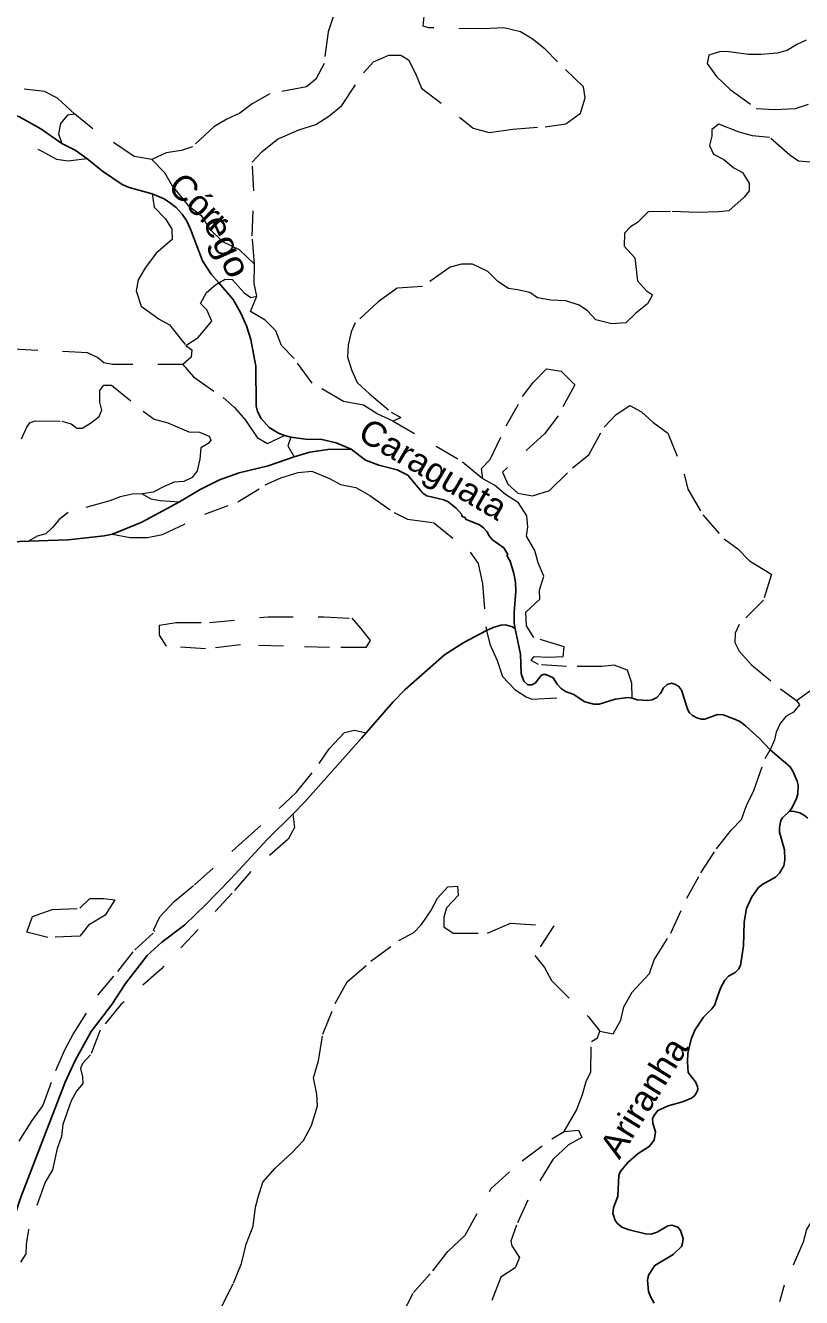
# Model space of a CAD drawing. Extents: x 344.9 to 371, y 7566.4 to 7594.3.
# Drawn here: x 359.71 to 362.82, y 7569.18 to 7574.28 of the extents above; entities that cross this region are included whole.
import ezdxf
from ezdxf.enums import TextEntityAlignment as Align

# ---------------------------------------------------------------- set-up
doc = ezdxf.new("R2010")
doc.units = 0
doc.header["$LTSCALE"] = 0.04
doc.linetypes.add('SHORT_DASHED', pattern=[2.7, 1.5, -1.2])
for name, color, linetype, lineweight in [('17', 7, 'SHORT_DASHED', 13), ('21', 7, 'SHORT_DASHED', 13), ('7', 7, 'Continuous', 25)]:
    doc.layers.add(name, color=color, linetype=linetype, lineweight=lineweight)
doc.layers.add('61', color=7, linetype='Continuous')

msp = doc.modelspace()

# ---------------------------------------------------------------- linework, layer by layer
at = {"layer": '17'}
for points in [[(359.9089, 7573.9225), (359.8797, 7573.9176), (359.8525, 7573.8846), (359.8447, 7573.8438), (359.8579, 7573.8042)], [(360.2178, 7573.741), (360.2676, 7573.6881), (360.2988, 7573.6356), (360.361, 7573.5579), (360.4154, 7573.517), (360.4484, 7573.4626), (360.5009, 7573.4121), (360.567, 7573.381), (360.6284, 7573.3223)], [(360.3538, 7572.9965), (360.4023, 7573.0285), (360.4577, 7573.0936), (360.4373, 7573.1393), (360.412, 7573.1636), (360.4363, 7573.2083), (360.4723, 7573.2394), (360.485, 7573.2467)], [(360.485, 7573.2467), (360.5112, 7573.2617), (360.5394, 7573.2607), (360.587, 7573.2073), (360.6132, 7573.1878), (360.6378, 7573.1937)], [(360.3421, 7572.9206), (360.3844, 7572.8711), (360.5031, 7572.7876), (360.5485, 7572.748), (360.5925, 7572.6967), (360.6394, 7572.6278), (360.6804, 7572.6044), (360.7483, 7572.6354)], [(361.1825, 7572.6938), (361.4606, 7572.5308), (361.5422, 7572.4628)], [(360.7742, 7572.6294), (360.7611, 7572.5941), (360.7863, 7572.551)], [(362.7973, 7571.5743), (362.9208, 7571.6646), (362.9714, 7571.7215), (363.0813, 7571.8908), (363.142, 7572.0033), (363.1724, 7572.1045), (363.2128, 7572.1677), (363.2596, 7572.2498), (363.3076, 7572.2903), (363.3606, 7572.3471), (363.444, 7572.4217), (363.4706, 7572.4444), (363.5199, 7572.4747), (363.568, 7572.5253), (363.5844, 7572.5493), (363.6311, 7572.5632), (363.6948, 7572.5426)], [(360.1786, 7572.4028), (360.2136, 7572.3821), (360.2503, 7572.3762), (360.3278, 7572.3706)], [(363.5011, 7570.3979), (363.3768, 7570.4345), (363.3159, 7570.429), (363.2845, 7570.3921), (363.2402, 7570.2519), (363.2199, 7570.2057), (363.1646, 7570.1578), (363.1148, 7570.1061), (363.0945, 7570.0342), (363.052, 7569.9456), (363.0354, 7569.8847), (363.0133, 7569.8312), (362.9764, 7569.7233), (362.9616, 7569.6402), (362.886, 7569.5388), (362.8362, 7569.4576), (362.8233, 7569.4059), (362.7477, 7569.2343), (362.7292, 7569.1679)], [(361.8672, 7569.8493), (361.917, 7569.9351), (361.941, 7569.9978), (361.9558, 7570.0495), (361.9742, 7570.0882), (361.9761, 7570.21), (362, 7570.2247), (362.0101, 7570.2504)]]:
    msp.add_lwpolyline(points, dxfattribs=at)
at = {"layer": '21'}
for points in [[(360.9488, 7574.328), (360.9229, 7574.2525), (360.9064, 7574.1252), (360.8734, 7574.0628), (360.8357, 7574.0321), (360.6894, 7574.0038), (360.6187, 7573.9637), (360.5692, 7573.926), (360.5173, 7573.9024), (360.4654, 7573.8718), (360.3805, 7573.7916), (360.3357, 7573.7763), (360.2744, 7573.7669), (360.2178, 7573.741)], [(360.6284, 7573.3223), (360.6189, 7573.4355), (360.626, 7573.6147), (360.6189, 7573.7302), (360.659, 7573.7727), (360.7203, 7573.8222), (360.8052, 7573.8599), (360.8736, 7573.8812), (360.9255, 7573.9142), (360.9774, 7573.9566), (361.0647, 7574.0875), (361.1047, 7574.1323), (361.1661, 7574.1583), (361.2132, 7574.1583), (361.2439, 7574.1394), (361.2722, 7574.0852), (361.2958, 7574.0262), (361.449, 7573.9107), (361.5033, 7573.8659), (361.567, 7573.8483), (361.6613, 7573.8624), (361.791, 7573.8718), (361.8735, 7573.8836), (361.9325, 7573.9261), (361.9514, 7573.9874), (361.9443, 7574.0322), (361.8405, 7574.1312), (361.791, 7574.1831), (361.7391, 7574.2232), (361.692, 7574.2515), (361.6259, 7574.268), (361.5457, 7574.2633), (361.3241, 7574.268), (361.3029, 7574.2751), (361.3076, 7574.3152)], [(362.8354, 7574.2179), (362.7977, 7574.2014), (362.76, 7574.1778), (362.7199, 7574.166), (362.6539, 7574.1613), (362.6043, 7574.1613), (362.5171, 7574.1731), (362.4888, 7574.172), (362.4464, 7574.1578), (362.4393, 7574.1248), (362.477, 7574.0729), (362.5312, 7574.0211), (362.635, 7573.9456), (362.7105, 7573.9409), (362.793, 7573.9456), (362.8449, 7573.9621)], [(359.9089, 7573.9225), (359.8405, 7573.9862), (359.7886, 7574.0134), (359.7061, 7574.0228)], [(359.5008, 7573.9208), (359.5798, 7573.8664), (359.78, 7573.7725), (359.8357, 7573.7416), (359.8822, 7573.7354), (359.9568, 7573.7445)], [(360.2178, 7573.741), (360.147, 7573.7527), (359.982, 7573.8636), (359.9089, 7573.9225)], [(362.852, 7573.7299), (362.8048, 7573.7346), (362.7695, 7573.7581), (362.6893, 7573.8289), (362.6209, 7573.836), (362.5667, 7573.8501), (362.4865, 7573.882), (362.4582, 7573.8608), (362.4582, 7573.8348), (362.4488, 7573.7971), (362.4653, 7573.7617), (362.5054, 7573.7405), (362.5455, 7573.7075), (362.5808, 7573.6886), (362.6068, 7573.6462), (362.6068, 7573.6155), (362.5879, 7573.5896), (362.5266, 7573.5353), (362.4865, 7573.5306), (362.3993, 7573.5283), (362.2932, 7573.533), (362.2035, 7573.5306), (362.1611, 7573.4882), (362.1328, 7573.4717), (362.1092, 7573.4457)], [(360.2195, 7573.6029), (360.2273, 7573.5494), (360.2721, 7573.5027), (360.2974, 7573.4618), (360.2993, 7573.4209), (360.2351, 7573.3664), (360.1922, 7573.308), (360.1631, 7573.2593), (360.1553, 7573.2146), (360.1747, 7573.1542), (360.2467, 7573.1016), (360.2876, 7573.0783), (360.3538, 7572.9965)], [(362.1092, 7573.4457), (362.1069, 7573.3939), (362.1493, 7573.3467), (362.1611, 7573.2549), (362.1965, 7573.2148), (362.2201, 7573.1983), (362.2012, 7573.1629), (362.1541, 7573.1252), (362.114, 7573.0875), (362.0574, 7573.0828), (361.9937, 7573.0993), (361.9607, 7573.1346), (361.9277, 7573.1582), (361.8734, 7573.1747), (361.8145, 7573.1771), (361.7602, 7573.1865), (361.7296, 7573.2077), (361.6801, 7573.2195), (361.6447, 7573.2242), (361.6023, 7573.2525), (361.5622, 7573.2926), (361.5009, 7573.3221), (361.4561, 7573.3221), (361.4113, 7573.3103), (361.3004, 7573.2325), (361.199, 7573.2254), (361.1236, 7573.1712), (361.0316, 7573.0863), (361.0151, 7573.051), (361.0033, 7572.9968), (361.0009, 7572.9496), (361.0174, 7572.8954), (361.0387, 7572.8482), (361.0882, 7572.8023), (361.1755, 7572.7292), (361.2132, 7572.7079), (361.1825, 7572.6938)], [(360.6378, 7573.1937), (360.6269, 7573.2439), (360.6284, 7573.3223)], [(361.1825, 7572.6938), (361.1189, 7572.7221), (361.0646, 7572.7575), (360.9845, 7572.7716), (360.8595, 7572.8447), (360.7864, 7572.9438), (360.7369, 7572.9956), (360.7133, 7573.0546), (360.6708, 7573.097), (360.6119, 7573.1324), (360.6378, 7573.1937)], [(360.3421, 7572.9206), (360.0598, 7572.9206), (360.0248, 7572.9264), (359.9995, 7572.9478), (359.9606, 7572.9673), (359.6277, 7572.9829)], [(360.3538, 7572.9965), (360.3771, 7572.979), (360.3752, 7572.9498), (360.3421, 7572.9206)], [(361.5422, 7572.4628), (361.5365, 7572.5033), (361.5714, 7572.5393), (361.6356, 7572.6743), (361.7009, 7572.7925), (361.7438, 7572.8477), (361.7967, 7572.9028), (361.8552, 7572.8927), (361.9103, 7572.8387), (361.8428, 7572.7149), (361.7888, 7572.6429), (361.62, 7572.4892), (361.6414, 7572.4409), (361.6819, 7572.4048), (361.7404, 7572.3936), (361.809, 7572.4161), (361.9002, 7572.5061), (361.9655, 7572.559), (362.0274, 7572.6698), (362.0758, 7572.7205), (362.1298, 7572.7554), (362.176, 7572.7306), (362.2221, 7572.689), (362.2818, 7572.6457), (362.3471, 7572.4814), (362.3617, 7572.4206), (362.4214, 7572.3188), (362.5069, 7572.222), (362.562, 7572.1815), (362.6093, 7572.1342), (362.6971, 7572.0807), (362.6645, 7571.9772), (362.5677, 7571.8793), (362.5509, 7571.8444), (362.5498, 7571.8073), (362.5678, 7571.7724), (362.6173, 7571.7172), (362.7321, 7571.6216), (362.7973, 7571.5743)], [(359.6958, 7572.6228), (359.7173, 7572.6695), (359.7289, 7572.687), (359.7503, 7572.6948), (359.8574, 7572.6929), (359.8944, 7572.6831), (359.9178, 7572.6656), (359.9392, 7572.6656), (359.9723, 7572.6851), (360.0073, 7572.7123), (360.017, 7572.7366), (360.0092, 7572.7697), (360.0092, 7572.8164), (360.0248, 7572.8379), (360.056, 7572.8379), (360.1825, 7572.7327), (360.2273, 7572.7016), (360.2818, 7572.686), (360.3655, 7572.651), (360.4083, 7572.649), (360.4472, 7572.6335), (360.453, 7572.617), (360.4433, 7572.6033), (360.4141, 7572.5858), (360.4102, 7572.541), (360.3985, 7572.4943), (360.3791, 7572.4671), (360.346, 7572.4515), (360.307, 7572.4496), (360.2662, 7572.432), (360.2233, 7572.4087), (360.1786, 7572.4028)], [(360.0605, 7572.2407), (360.131, 7572.2268), (360.1996, 7572.2279), (360.2604, 7572.2392), (360.4292, 7572.3202), (360.5619, 7572.3697), (360.6711, 7572.4383), (360.733, 7572.4665), (360.8028, 7572.4879), (360.8579, 7572.4935), (360.9277, 7572.4642), (360.9727, 7572.4395), (361.0335, 7572.4276), (361.0898, 7572.3961), (361.1877, 7572.3275), (361.2406, 7572.3005), (361.3441, 7572.287), (361.4905, 7572.1693), (361.5231, 7572.1232), (361.5411, 7572.0422), (361.5536, 7571.8694), (361.5569, 7571.8551)], [(362.1387, 7571.5844), (362.1373, 7571.6442), (362.1205, 7571.696), (362.0676, 7571.7162), (362.0192, 7571.7106), (361.8763, 7571.7106), (361.7649, 7571.719), (361.7357, 7571.7348), (361.7469, 7571.7516), (361.8043, 7571.7483), (361.8628, 7571.7505), (361.8673, 7571.7899), (361.7458, 7571.827), (361.7165, 7571.8732), (361.7132, 7571.9283), (361.7694, 7571.9812), (361.7683, 7572.0166), (361.7852, 7572.0729), (361.7627, 7572.1258), (361.7503, 7572.1753), (361.7166, 7572.2327), (361.7222, 7572.2704), (361.7177, 7572.3143), (361.6839, 7572.366), (361.6322, 7572.3998), (361.5883, 7572.4369), (361.5422, 7572.4628)], [(360.1786, 7572.4028), (360.1396, 7572.4009), (360.0909, 7572.3902), (360.0501, 7572.3746), (359.8827, 7572.3279), (359.8457, 7572.2987), (359.8204, 7572.2676), (359.7931, 7572.2423), (359.7581, 7572.2325), (359.7247, 7572.2132)], [(361.5569, 7571.8551), (361.5693, 7571.8008), (361.5997, 7571.7344), (361.6201, 7571.6708), (361.6696, 7571.619), (361.7157, 7571.5898), (361.7382, 7571.5796), (361.919, 7571.5901), (361.92, 7571.5901), (361.9196, 7571.5897)], [(362.7973, 7571.5743), (362.8086, 7571.5569), (362.785, 7571.5287), (362.7546, 7571.5107), (362.731, 7571.4826), (362.7152, 7571.4477), (362.7085, 7571.4173), (362.6908, 7571.3768)], [(359.6871, 7569.8106), (359.7385, 7569.8935), (359.7819, 7569.9528), (359.8332, 7570.093), (359.8688, 7570.1759), (359.9023, 7570.2391), (360.001, 7570.3951), (360.0819, 7570.4899), (360.1491, 7570.5768), (360.23, 7570.6498), (360.2241, 7570.6557), (360.2498, 7570.7091), (360.307, 7570.7703), (360.388, 7570.8374), (360.5795, 7571.0072), (360.7967, 7571.2076), (360.8876, 7571.3221), (360.9271, 7571.3814), (360.9883, 7571.4465), (361.0278, 7571.4564), (361.0744, 7571.4453)], [(362.0101, 7570.2504), (362.0631, 7570.2406), (362.0945, 7570.2955), (362.1063, 7570.3485), (362.1396, 7570.4074), (362.2083, 7570.4819), (362.2279, 7570.5369), (362.2946, 7570.6428), (362.3574, 7570.7831), (362.4143, 7570.8851), (362.4771, 7570.9813), (362.536, 7571.0558), (362.5772, 7571.099), (362.5968, 7571.1539), (362.6262, 7571.2148), (362.6713, 7571.3433), (362.6908, 7571.3768)], [(360.7818, 7571.1194), (360.788, 7571.0669), (360.7634, 7571.0201), (360.6132, 7570.8908), (360.5393, 7570.8034), (360.2561, 7570.5011), (360.0936, 7570.3576), (360.0103, 7570.2548), (359.9722, 7570.1563), (359.9401, 7570.1218), (359.9315, 7570.1021), (359.9401, 7570.0676), (359.9414, 7570.0417), (359.9167, 7570.011), (359.8946, 7569.9715), (359.8613, 7569.8779), (359.8564, 7569.8293), (359.8392, 7569.7812), (359.8195, 7569.6963), (359.7912, 7569.647), (359.7235, 7569.4568), (359.7148, 7569.3976), (359.7136, 7569.3595), (359.6914, 7569.3262)], [(360.4972, 7569.1506), (360.5443, 7569.2428), (360.5756, 7569.3213), (360.5953, 7569.3978), (360.6227, 7569.4704), (360.6326, 7569.5469), (360.6424, 7569.5871), (360.662, 7569.646), (360.7111, 7569.7029), (360.7778, 7569.7637), (360.8249, 7569.8128), (360.8563, 7569.8736), (360.8798, 7569.9521), (360.8779, 7569.9992), (360.8642, 7570.064), (360.8838, 7570.1327), (360.9015, 7570.2386), (360.9505, 7570.3622), (360.9996, 7570.4486), (361.0938, 7570.531), (361.2056, 7570.6134), (361.2664, 7570.6467), (361.2959, 7570.6781), (361.3332, 7570.7331), (361.3606, 7570.7841), (361.4018, 7570.8292), (361.4411, 7570.8312), (361.443, 7570.7939), (361.3959, 7570.7448), (361.3861, 7570.7076), (361.3861, 7570.6683), (361.4234, 7570.6428), (361.5608, 7570.6428), (361.6527, 7570.6833), (361.8258, 7570.6721), (361.7492, 7570.5535), (361.7884, 7570.5064), (361.8159, 7570.4535), (361.965, 7570.3083), (362.0101, 7570.2504)], [(361.8672, 7569.8493), (361.9242, 7569.8552), (361.9379, 7569.8258), (361.8849, 7569.7964), (361.8221, 7569.7375), (361.722, 7569.5746), (361.6769, 7569.4746), (361.6534, 7569.4098), (361.6573, 7569.3922), (361.6887, 7569.3451), (361.671, 7569.3039), (361.6141, 7569.2666), (361.5552, 7569.1126)], [(360.9097, 7568.6426), (360.8607, 7568.6936), (360.8312, 7568.7427), (360.8371, 7568.7917), (361.1216, 7569.0194), (361.2178, 7569.1135), (361.2649, 7569.2048), (361.3414, 7569.2911), (361.4022, 7569.3696), (361.4709, 7569.4343), (361.5749, 7569.6207), (361.6985, 7569.7326), (361.8182, 7569.8199), (361.8672, 7569.8493)]]:
    msp.add_lwpolyline(points, dxfattribs=at)
for points in [[(360.2756, 7571.7923), (360.2477, 7571.8371), (360.2477, 7571.8763), (360.3147, 7571.8875), (360.4487, 7571.8875), (360.6832, 7571.9099), (360.9066, 7571.9099), (361.0183, 7571.9043), (361.0518, 7571.8651), (361.0908, 7571.8147), (361.0741, 7571.7867), (360.9289, 7571.7867), (360.7447, 7571.7923), (360.5716, 7571.7979), (360.432, 7571.7811)], [(359.7178, 7570.6479), (359.7401, 7570.7095), (359.8183, 7570.7375), (359.93, 7570.7431), (359.9691, 7570.7823), (360.0249, 7570.7823), (360.0696, 7570.7767), (360.0305, 7570.7151), (359.9635, 7570.6759), (359.93, 7570.6311), (359.8016, 7570.6255)]]:
    msp.add_lwpolyline(points, close=True, dxfattribs=at)
at = {"layer": '7'}
for points in [[(359.5008, 7573.9208), (359.5792, 7573.9284), (359.6378, 7573.9249), (359.6858, 7573.9127), (359.7734, 7573.8635), (359.8579, 7573.8042)], [(359.8579, 7573.8042), (359.9105, 7573.7781), (359.9568, 7573.7445)], [(359.9568, 7573.7445), (360.0198, 7573.694), (360.0987, 7573.6407), (360.1268, 7573.6285), (360.2195, 7573.6029)], [(360.2195, 7573.6029), (360.2662, 7573.5833), (360.2888, 7573.569), (360.3146, 7573.5482), (360.3386, 7573.5217), (360.3557, 7573.4972), (360.3718, 7573.4614), (360.4203, 7573.335), (360.4549, 7573.2812), (360.485, 7573.2467)], [(360.485, 7573.2467), (360.543, 7573.1802), (360.5734, 7573.1255), (360.5965, 7573.075), (360.6136, 7573.0208), (360.6339, 7572.9128), (360.6348, 7572.7548), (360.6408, 7572.7324), (360.6556, 7572.7033), (360.6874, 7572.6675), (360.7239, 7572.6456), (360.7483, 7572.6354), (360.7742, 7572.6294), (360.8319, 7572.6209)], [(360.8319, 7572.6209), (360.8974, 7572.6193), (360.9555, 7572.6061), (361.0154, 7572.5809)], [(361.0154, 7572.5809), (360.921, 7572.58), (360.85, 7572.5692), (360.7863, 7572.551)], [(361.0154, 7572.5809), (361.0722, 7572.5375), (361.1257, 7572.517), (361.1991, 7572.4988), (361.2412, 7572.4775), (361.3015, 7572.4053), (361.3174, 7572.3941), (361.3857, 7572.3783), (361.4032, 7572.3703), (361.4349, 7572.3449), (361.4579, 7572.3195), (361.4579, 7572.3123), (361.473, 7572.306), (361.473, 7572.3013), (361.5286, 7572.2782), (361.5445, 7572.2663), (361.558, 7572.252), (361.5675, 7572.2338), (361.581, 7572.2179), (361.6255, 7572.1861), (361.6414, 7572.1591), (361.6374, 7572.1559), (361.6517, 7572.1321), (361.666, 7572.0829), (361.6723, 7572.048), (361.6739, 7572.013), (361.6668, 7571.9273), (361.6668, 7571.8844), (361.6716, 7571.8612)], [(360.7863, 7572.551), (360.6825, 7572.5138), (360.5667, 7572.4866), (360.4878, 7572.4587), (360.4108, 7572.4202), (360.3278, 7572.3706)], [(360.3278, 7572.3706), (360.1778, 7572.2894), (360.0605, 7572.2407)], [(359.7247, 7572.2132), (359.6527, 7572.2102), (359.555, 7572.1994), (359.4774, 7572.1991), (359.4166, 7572.2053), (359.292, 7572.2372), (359.2702, 7572.2401), (359.248, 7572.2417), (359.1781, 7572.2369), (359.1067, 7572.2187), (359.0622, 7572.2107), (358.9971, 7572.1845), (358.8839, 7572.1306), (358.835, 7572.113), (358.8192, 7572.1035), (358.7509, 7572.0853), (358.6794, 7572.0749), (358.5746, 7572.0495), (358.5254, 7572.032), (358.4714, 7572.0249), (358.411, 7572.005), (358.3221, 7571.9598)], [(360.0605, 7572.2407), (360.0264, 7572.2335), (359.8824, 7572.2178), (359.7247, 7572.2132)], [(361.0744, 7571.4453), (361.1832, 7571.5702), (361.2307, 7571.6184), (361.3881, 7571.7575), (361.4656, 7571.8076), (361.5569, 7571.8551)], [(361.5569, 7571.8551), (361.5837, 7571.8676), (361.6132, 7571.8764), (361.6321, 7571.8776), (361.6607, 7571.8697), (361.6716, 7571.8612)], [(361.6716, 7571.8612), (361.6922, 7571.7605), (361.6953, 7571.6827), (361.7057, 7571.6525), (361.7216, 7571.6374), (361.7383, 7571.6382), (361.751, 7571.6445), (361.7763, 7571.6763), (361.7835, 7571.6795), (361.7939, 7571.6787), (361.8232, 7571.6652), (361.8391, 7571.6406), (361.8549, 7571.6231), (361.8729, 7571.6114)], [(362.1387, 7571.5844), (362.1595, 7571.5782), (362.2014, 7571.5749), (362.2189, 7571.5774), (362.2374, 7571.5867), (362.2521, 7571.6024), (362.2646, 7571.625), (362.2794, 7571.6391), (362.2969, 7571.6437), (362.3098, 7571.64), (362.3241, 7571.6317), (362.3366, 7571.6165), (362.362, 7571.538), (362.3684, 7571.5251), (362.3804, 7571.5149), (362.3984, 7571.505), (362.4155, 7571.5004), (362.4302, 7571.5008), (362.4805, 7571.5182), (362.5035, 7571.5177), (362.5529, 7571.4985), (362.5727, 7571.4889), (362.593, 7571.4732), (362.647, 7571.4236), (362.6908, 7571.3768)], [(361.8729, 7571.6114), (361.9061, 7571.5984), (361.919, 7571.5901), (361.9196, 7571.5897)], [(361.9196, 7571.5897), (361.95, 7571.5701), (361.986, 7571.5599), (362.0072, 7571.5604), (362.0709, 7571.58), (362.1235, 7571.5867), (362.1387, 7571.5844)], [(360.7818, 7571.1194), (360.8313, 7571.1705), (361.0559, 7571.4241), (361.0744, 7571.4453)], [(362.6908, 7571.3768), (362.7711, 7571.309), (362.7835, 7571.2896), (362.7997, 7571.2524), (362.8034, 7571.2363), (362.8016, 7571.2014), (362.7961, 7571.182), (362.778, 7571.1435), (362.7678, 7571.1301)], [(362.7678, 7571.1301), (362.7402, 7571.1056), (362.7337, 7571.0943), (362.7291, 7571.0671), (362.7282, 7571.0479), (362.7485, 7570.977), (362.7494, 7570.9366), (362.7461, 7570.913), (362.7286, 7570.8837), (362.7129, 7570.868), (362.6621, 7570.8392), (362.6441, 7570.8258), (362.6174, 7570.7891), (362.5967, 7570.7428), (362.5875, 7570.6872), (362.5847, 7570.5921), (362.5732, 7570.5139), (362.5649, 7570.4998), (362.5511, 7570.4859), (362.5248, 7570.4707), (362.51, 7570.4557), (362.4925, 7570.4238), (362.4767, 7570.3772)], [(362.8425, 7571.1035), (362.8293, 7571.1149), (362.8103, 7571.1245), (362.7821, 7571.1319), (362.7678, 7571.1301)], [(359.5577, 7569.1956), (359.5767, 7569.2448), (359.5815, 7569.248), (359.5799, 7569.2536), (359.5886, 7569.283), (359.6252, 7569.383), (359.6339, 7569.3989), (359.6426, 7569.4338), (359.6935, 7569.5863), (359.8713, 7570.0469), (359.911, 7570.1342), (359.9753, 7570.2502), (360.0571, 7570.3581), (360.1127, 7570.4423), (360.1989, 7570.5544), (360.257, 7570.6072), (360.3498, 7570.6773), (360.4323, 7570.7569), (360.5342, 7570.8612), (360.6794, 7571.0184), (360.7818, 7571.1194)], [(362.4767, 7570.3772), (362.4696, 7570.3565), (362.4577, 7570.3399), (362.4251, 7570.3073), (362.3902, 7570.2549), (362.3759, 7570.2184), (362.3616, 7570.1628), (362.36, 7570.1279), (362.3632, 7570.0858), (362.3926, 7570.0485), (362.4013, 7570.0294), (362.4021, 7570.019), (362.3989, 7570.0095), (362.3902, 7569.9936), (362.3767, 7569.9825), (362.3402, 7569.9682), (362.283, 7569.9515), (362.2512, 7569.9378), (362.2425, 7569.9333), (362.2282, 7569.9166), (362.221, 7569.9008), (362.2218, 7569.8833), (362.2321, 7569.8483), (362.2274, 7569.8142), (362.2068, 7569.7895), (362.1639, 7569.7617), (362.1219, 7569.7253), (362.0915, 7569.6884), (362.0859, 7569.6732), (362.0818, 7569.5902), (362.0652, 7569.5434), (362.0625, 7569.5221), (362.0717, 7569.4929), (362.0809, 7569.4804), (362.098, 7569.4661), (362.1275, 7569.4557), (362.1925, 7569.4398), (362.2156, 7569.4389), (362.2391, 7569.4463), (362.282, 7569.4715), (362.2986, 7569.4747), (362.3222, 7569.4659), (362.3332, 7569.4535), (362.3434, 7569.4214), (362.3411, 7569.4021), (362.336, 7569.3889), (362.3028, 7569.3575), (362.2303, 7569.313), (362.2045, 7569.2742), (362.2008, 7569.2539), (362.2045, 7569.2084), (362.2133, 7569.1856), (362.2272, 7569.1621)]]:
    msp.add_lwpolyline(points, dxfattribs=at)

# ---------------------------------------------------------------- texts
at = {"layer": '61'}
for s, rotation, width, p in [('Córr', 315.864, 1.05, (360.3734, 7573.5315)), ('ego', 294.427, 1.15, (360.4742, 7573.3734)), ('Caraguata', 329.582, 1.05, (361.3184, 7572.4586)), ('Ariranha', 58.32, 1.05, (362.2274, 7569.9598))]:
    msp.add_text(s, height=0.1, rotation=rotation, dxfattribs=dict(at, width=width)).set_placement(p, align=Align.CENTER)

doc.saveas('drawing.dxf')
